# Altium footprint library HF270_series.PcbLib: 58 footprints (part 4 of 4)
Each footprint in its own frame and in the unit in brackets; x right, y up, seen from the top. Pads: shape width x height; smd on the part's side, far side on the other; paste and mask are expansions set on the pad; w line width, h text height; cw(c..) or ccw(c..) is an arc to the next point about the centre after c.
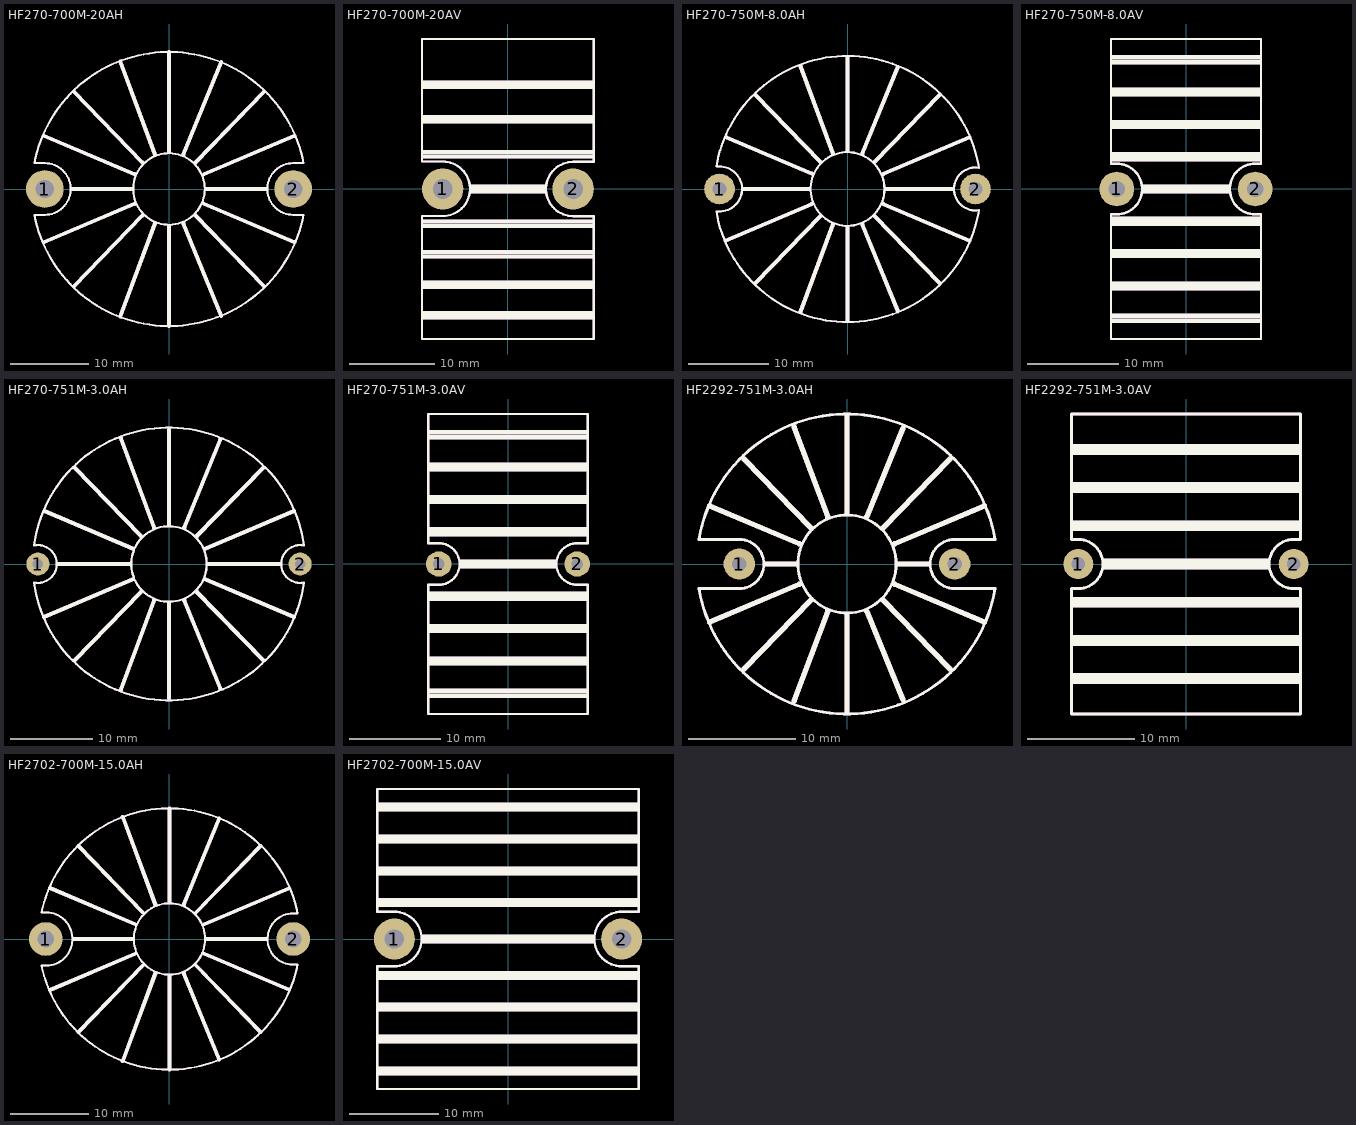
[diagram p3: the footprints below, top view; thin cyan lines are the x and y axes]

## HF270-700M-20AH [mil]
pads (2):
  round 190 hole 92: 1(-625,0) 2(625,0)
Top Overlay:
  circle w10: c0,0 r180
  lines w10: -677.61,-130.18 ccw(c0,0) 677.67,-129.86 ; -677.61,130.18 cw(c0,0) 677.64,130 625,130 ccw(c625,0) 625,-130 677.67,-130 ; -676.66,-130 -625,-130 ccw(c-625,0) -625,130 -676.66,130
  lines w19.68: -630.61,-268.56 -173.05,-74.68 ; -630.61,268.56 -173.05,74.68 ; -485,0 -185,0 ; -479.51,-490.47 -132.7,-132.43 ; -479.51,490.47 -132.7,132.43 ; -245.53,-641.67 -70.44,-171.87 ; -245.53,641.67 -70.44,171.87 ; 0,-690 0,-185 ; 0,185 0,690 ; 72.46,-173.99 262.95,-638.79 ; 72.46,173.99 262.95,638.79 ; 132.5,-132.5 479.53,-490.46 ; 132.5,132.5 479.53,490.46 ; 175.3,-74.28 631.1,-267.41 ; 175.3,74.28 631.1,267.41 ; 185,0 490,0
Mechanical 29:
  circle w10: c0,0 r180
  lines w10: -677.61,-130.18 ccw(c0,0) 677.67,-129.86 ; -677.61,130.18 cw(c0,0) 677.64,130 625,130 ccw(c625,0) 625,-130 677.67,-130 ; -676.66,-130 -625,-130 ccw(c-625,0) -625,130 -676.66,130
  lines w19.68: -630.61,-268.56 -173.05,-74.68 ; -630.61,268.56 -173.05,74.68 ; -485,0 -185,0 ; -479.51,-490.47 -132.7,-132.43 ; -479.51,490.47 -132.7,132.43 ; -245.53,-641.67 -70.44,-171.87 ; -245.53,641.67 -70.44,171.87 ; 0,-690 0,-185 ; 0,185 0,690 ; 72.46,-173.99 262.95,-638.79 ; 72.46,173.99 262.95,638.79 ; 132.5,-132.5 479.53,-490.46 ; 132.5,132.5 479.53,490.46 ; 175.3,-74.28 631.1,-267.41 ; 175.3,74.28 631.1,267.41 ; 185,0 490,0
  text "'.Designator'" at -300,175.15 h400

## HF270-700M-20AV [mil]
pads (2):
  round 190 hole 90: 1(-300,0) 2(300,0)
Top Overlay:
  lines w10: -395,-124.1 -395,-690 395,-690 395,-125 300,-125 cw(c300,0) 300,125 395,125 395,690 -395,690 -395,125.9 ; -394.45,-124.1 -299.45,-124.1 ccw(c-299.45,0.9) -299.45,125.9 -394.45,125.9
  lines w19.68: -390,-590 390,-590 ; -390,-570 390,-570 ; -390,-450 390,-450 ; -390,-430 390,-430 ; -390,-310 390,-310 ; -390,-290 390,-290 ; -390,-170 390,-170 ; -390,-150 390,-150 ; -390,150 390,150 ; -390,170 390,170 ; -390,310 390,310 ; -390,330 390,330 ; -390,470 390,470 ; -390,490 390,490 ; -170,-10 170,-10 ; -170,10 170,10
Mechanical 29:
  lines w10: -395,-124.1 -395,-690 395,-690 395,-125 300,-125 cw(c300,0) 300,125 395,125 395,690 -395,690 -395,125.9 ; -394.45,-124.1 -299.45,-124.1 ccw(c-299.45,0.9) -299.45,125.9 -394.45,125.9
  lines w19.68: -390,-590 390,-590 ; -390,-570 390,-570 ; -390,-450 390,-450 ; -390,-430 390,-430 ; -390,-310 390,-310 ; -390,-290 390,-290 ; -390,-170 390,-170 ; -390,-150 390,-150 ; -390,150 390,150 ; -390,170 390,170 ; -390,310 390,310 ; -390,330 390,330 ; -390,470 390,470 ; -390,490 390,490 ; -170,-10 170,-10 ; -170,10 170,10
  text "'.Designator'" at -1750,-64.85 h400

## HF270-750M-8.0AH [mil]
pads (2):
  round 150 hole 70: 1(-625,0) 2(625,0)
Top Overlay:
  circle w10: c0,0 r180
  lines w10: -640.72,109.47 cw(c0,0) 641.68,103.67 ccw(c625,0) 641.68,-103.67 cw(c0,0) -640.82,-108.86 ccw(c-625,0) -638.75,109.14
  lines w19.68: -596.03,-252.56 -175.3,-74.28 ; -593.79,252.95 -173.05,74.68 ; -510,0 -185,0 ; -450,-460 -132.7,-132.43 ; -450,460 -132.7,132.43 ; -230,-600 -70.44,-171.87 ; -230,600 -70.44,171.87 ; 0,-640 0,-185 ; 0,185 0,640 ; 72.46,-173.99 243.97,-592.47 ; 72.46,173.99 243.97,592.47 ; 132.5,-132.5 450,-460 ; 132.5,132.5 450,460 ; 175.3,-74.28 596.03,-252.56 ; 175.3,74.28 596.03,252.56 ; 185,0 515,0
Mechanical 29:
  circle w10: c0,0 r180
  lines w10: -640.72,109.47 cw(c0,0) 641.68,103.67 ccw(c625,0) 641.68,-103.67 cw(c0,0) -640.82,-108.86 ccw(c-625,0) -638.75,109.14
  lines w19.68: -596.03,-252.56 -175.3,-74.28 ; -593.79,252.95 -173.05,74.68 ; -510,0 -185,0 ; -450,-460 -132.7,-132.43 ; -450,460 -132.7,132.43 ; -230,-600 -70.44,-171.87 ; -230,600 -70.44,171.87 ; 0,-640 0,-185 ; 0,185 0,640 ; 72.46,-173.99 243.97,-592.47 ; 72.46,173.99 243.97,592.47 ; 132.5,-132.5 450,-460 ; 132.5,132.5 450,460 ; 175.3,-74.28 596.03,-252.56 ; 175.3,74.28 596.03,252.56 ; 185,0 515,0
  text "'.Designator'" at -290,145.15 h400

## HF270-750M-8.0AV [mil]
pads (2):
  round 150 hole 70: 1(-300,0) 2(300,0)
Top Overlay:
  lines w10: -325,-650 -325,-110 -300,-110 ccw(c-300,0) -300,110 -325,110 -325,650 325,650 325,110 300,110 ccw(c300,0) 300,-110 325,-110 325,-650 -325,-650
  lines w19.68: -320,-570 320,-570 ; -320,-550 320,-550 ; -320,-430 320,-430 ; -320,-410 320,-410 ; -320,-290 320,-290 ; -320,-270 320,-270 ; -320,-150 320,-150 ; -320,-130 320,-130 ; -320,130 320,130 ; -320,150 320,150 ; -320,270 320,270 ; -320,290 320,290 ; -320,410 320,410 ; -320,430 320,430 ; -320,550 320,550 ; -320,570 320,570 ; -185,-10 185,-10 ; -185,10 185,10
Mechanical 29:
  lines w10: -325,-650 -325,-110 -300,-110 ccw(c-300,0) -300,110 -325,110 -325,650 325,650 325,110 300,110 ccw(c300,0) 300,-110 325,-110 325,-650 -325,-650
  lines w19.68: -320,-570 320,-570 ; -320,-550 320,-550 ; -320,-430 320,-430 ; -320,-410 320,-410 ; -320,-290 320,-290 ; -320,-270 320,-270 ; -320,-150 320,-150 ; -320,-130 320,-130 ; -320,130 320,130 ; -320,150 320,150 ; -320,270 320,270 ; -320,290 320,290 ; -320,410 320,410 ; -320,430 320,430 ; -320,550 320,550 ; -320,570 320,570 ; -185,-10 185,-10 ; -185,10 185,10
  text "'.Designator'" at -1750,-64.85 h400

## HF270-751M-3.0AH [mil]
pads (2):
  round 110 hole 50: 1(-625,0) 2(625,0)
Top Overlay:
  circle w10: c0,0 r180
  lines w10: -644.02,-87.97 ccw(c0,0) 644.02,-87.97 cw(c625,0) 644.02,87.97 ccw(c0,0) -644.02,87.97 cw(c-625,0) -644.02,-87.97
  lines w19.68: -596.03,-252.56 -175.3,-74.28 ; -593.79,252.95 -173.05,74.68 ; -530,0 -185,0 ; -450,-460 -132.7,-132.43 ; -450,460 -132.7,132.43 ; -230,-600 -70.44,-171.87 ; -230,600 -70.44,171.87 ; 0,-640 0,-185 ; 0,185 0,640 ; 72.46,-173.99 243.97,-592.47 ; 72.46,173.99 243.97,592.47 ; 132.5,-132.5 450,-460 ; 132.5,132.5 450,460 ; 175.3,-74.28 596.03,-252.56 ; 175.3,74.28 596.03,252.56 ; 185,0 530,0
Mechanical 29:
  circle w10: c0,0 r180
  lines w10: -644.02,-87.97 ccw(c0,0) 644.02,-87.97 cw(c625,0) 644.02,87.97 ccw(c0,0) -644.02,87.97 cw(c-625,0) -644.02,-87.97
  lines w19.68: -596.03,-252.56 -175.3,-74.28 ; -593.79,252.95 -173.05,74.68 ; -530,0 -185,0 ; -450,-460 -132.7,-132.43 ; -450,460 -132.7,132.43 ; -230,-600 -70.44,-171.87 ; -230,600 -70.44,171.87 ; 0,-640 0,-185 ; 0,185 0,640 ; 72.46,-173.99 243.97,-592.47 ; 72.46,173.99 243.97,592.47 ; 132.5,-132.5 450,-460 ; 132.5,132.5 450,460 ; 175.3,-74.28 596.03,-252.56 ; 175.3,74.28 596.03,252.56 ; 185,0 530,0
  text "'.Designator'" at -290,145.15 h400

## HF270-751M-3.0AV [mil]
pads (2):
  round 110 hole 50: 1(-300,0) 2(300,0)
Top Overlay:
  lines w10: -345,-650 -345,-90 -300,-90 ccw(c-300,0) -300,90 -345,90 -345,650 345,650 345,90 300,90 ccw(c300,0) 300,-90 345,-90 345,-650 -345,-650
  lines w19.68: -340,-570 340,-570 ; -340,-550 340,-550 ; -340,-430 340,-430 ; -340,-410 340,-410 ; -340,-290 340,-290 ; -340,-270 340,-270 ; -340,-150 340,-150 ; -340,-130 340,-130 ; -340,130 340,130 ; -340,150 340,150 ; -340,270 340,270 ; -340,290 340,290 ; -340,410 340,410 ; -340,430 340,430 ; -340,550 340,550 ; -340,570 340,570 ; -205,-10 205,-10 ; -205,10 205,10
Mechanical 29:
  lines w10: -345,-650 -345,-90 -300,-90 ccw(c-300,0) -300,90 -345,90 -345,650 345,650 345,90 300,90 ccw(c300,0) 300,-90 345,-90 345,-650 -345,-650
  lines w19.68: -340,-570 340,-570 ; -340,-550 340,-550 ; -340,-430 340,-430 ; -340,-410 340,-410 ; -340,-290 340,-290 ; -340,-270 340,-270 ; -340,-150 340,-150 ; -340,-130 340,-130 ; -340,130 340,130 ; -340,150 340,150 ; -340,270 340,270 ; -340,290 340,290 ; -340,410 340,410 ; -340,430 340,430 ; -340,550 340,550 ; -340,570 340,570 ; -205,-10 205,-10 ; -205,10 205,10
  text "'.Designator'" at -1750,-64.85 h400

## HF2292-751M-3.0AH [mil]
pads (2):
  round 115 hole 52: 1(-395,0) 2(395,0)
Top Overlay:
  circle w10: c0,0 r180
  lines w10: -543.19,-90 -395,-90 ccw(c-395,0) -395,90 -543.19,90 ; -542.59,-90 ccw(c0,0) 542.6,-89.9 ; -542.6,89.9 cw(c0,0) 542.59,90 ; 543.19,-90 395,-90 cw(c395,0) 395,90 543.19,90
  lines w19.68: -502.92,-213.1 -175.3,-74.28 ; -502.92,213.1 -175.3,74.28 ; -376.13,-383.74 -132.7,-132.43 ; -376.13,383.74 -132.7,132.43 ; -300,0 -185,0 ; -193.62,-502.38 -70.44,-171.87 ; -193.62,502.38 -70.44,171.87 ; 0,-540 0,-185 ; 0,185 0,540 ; 72.46,-173.99 205.19,-497.87 ; 72.46,173.99 205.19,497.87 ; 132.5,-132.5 376.1,-383.78 ; 132.5,132.5 376.1,383.78 ; 175.3,-74.28 502.92,-213.1 ; 175.3,74.28 502.92,213.1 ; 185,0 300,0
Mechanical 29:
  circle w10: c0,0 r180
  lines w10: -543.19,-90 -395,-90 ccw(c-395,0) -395,90 -543.19,90 ; -542.59,-90 ccw(c0,0) 542.6,-89.9 ; -542.6,89.9 cw(c0,0) 542.59,90 ; 543.19,-90 395,-90 cw(c395,0) 395,90 543.19,90
  lines w19.68: -502.92,-213.1 -175.3,-74.28 ; -502.92,213.1 -175.3,74.28 ; -376.13,-383.74 -132.7,-132.43 ; -376.13,383.74 -132.7,132.43 ; -300,0 -185,0 ; -193.62,-502.38 -70.44,-171.87 ; -193.62,502.38 -70.44,171.87 ; 0,-540 0,-185 ; 0,185 0,540 ; 72.46,-173.99 205.19,-497.87 ; 72.46,173.99 205.19,497.87 ; 132.5,-132.5 376.1,-383.78 ; 132.5,132.5 376.1,383.78 ; 175.3,-74.28 502.92,-213.1 ; 175.3,74.28 502.92,213.1 ; 185,0 300,0
  text "'.Designator'" at -290,145.15 h400

## HF2292-751M-3.0AV [mil]
pads (2):
  round 110 hole 50: 1(-395,0) 2(395,0)
Top Overlay:
  lines w10: -420,-550 420,-550 420,-90 395,-90 cw(c395,0) 395,90 420,90 420,550 -420,550 -420,90 -395,90 cw(c-395,0) -395,-90 -420,-90 -420,-550
  lines w19.68: -415,-430 415,-430 ; -415,-410 415,-410 ; -415,-290 415,-290 ; -415,-270 415,-270 ; -415,-150 415,-150 ; -415,-130 415,-130 ; -415,130 415,130 ; -415,150 415,150 ; -415,270 415,270 ; -415,290 415,290 ; -415,410 415,410 ; -415,430 415,430 ; -300,-10 300,-10 ; -300,10 300,10
Mechanical 29:
  lines w10: -420,-550 420,-550 420,-90 395,-90 cw(c395,0) 395,90 420,90 420,550 -420,550 -420,90 -395,90 cw(c-395,0) -395,-90 -420,-90 -420,-550
  lines w19.68: -415,-430 415,-430 ; -415,-410 415,-410 ; -415,-290 415,-290 ; -415,-270 415,-270 ; -415,-150 415,-150 ; -415,-130 415,-130 ; -415,130 415,130 ; -415,150 415,150 ; -415,270 415,270 ; -415,290 415,290 ; -415,410 415,410 ; -415,430 415,430 ; -300,-10 300,-10 ; -300,10 300,10
  text "'.Designator'" at -1750,-64.85 h400

## HF2702-700M-15.0AH [mil]
pads (2):
  round 170 hole 85: 1(-625,0) 2(625,0)
Top Overlay:
  circle w10: c0,0 r180
  lines w10: -646.24,-134.05 ccw(c0,0) 647.3,-128.86 ; -646.24,134.05 cw(c0,0) 647.18,129.44 ; -645.53,133.43 cw(c-625,0) -644.78,-133.54 ; 646.05,-128.28 cw(c625,0) 646.85,128.15
  lines w19.68: -604.03,-257.29 -173.05,-74.68 ; -604.03,257.29 -173.05,74.68 ; -485,0 -185,0 ; -459.92,-470.24 -132.7,-132.43 ; -459.92,470.24 -132.7,132.43 ; -236.54,-617.56 -70.44,-171.87 ; -236.54,617.56 -70.44,171.87 ; 0,-660 0,-185 ; 0,185 0,660 ; 72.46,-173.99 250.98,-609.6 ; 72.46,173.99 250.98,609.6 ; 132.5,-132.5 459.84,-470.15 ; 132.5,132.5 459.84,470.15 ; 175.3,-74.28 604.51,-256.15 ; 175.3,74.28 604.51,256.15 ; 185,0 490,0
Mechanical 29:
  circle w10: c0,0 r180
  lines w10: -646.24,-134.05 ccw(c0,0) 647.3,-128.86 ; -646.24,134.05 cw(c0,0) 647.18,129.44 ; -645.53,133.43 cw(c-625,0) -644.78,-133.54 ; 646.05,-128.28 cw(c625,0) 646.85,128.15
  lines w19.68: -604.03,-257.29 -173.05,-74.68 ; -604.03,257.29 -173.05,74.68 ; -485,0 -185,0 ; -459.92,-470.24 -132.7,-132.43 ; -459.92,470.24 -132.7,132.43 ; -236.54,-617.56 -70.44,-171.87 ; -236.54,617.56 -70.44,171.87 ; 0,-660 0,-185 ; 0,185 0,660 ; 72.46,-173.99 250.98,-609.6 ; 72.46,173.99 250.98,609.6 ; 132.5,-132.5 459.84,-470.15 ; 132.5,132.5 459.84,470.15 ; 175.3,-74.28 604.51,-256.15 ; 175.3,74.28 604.51,256.15 ; 185,0 490,0
  text "'.Designator'" at -292,168.15 h400

## HF2702-700M-15.0AV [mil]
pads (2):
  round 180 hole 85: 1(-500,0) 2(500,0)
Top Overlay:
  lines w10: -575,-660 575,-660 575,-120 500,-120 cw(c500,0) 500,120 575,120 575,660 -575,660 -575,120 -500,120 cw(c-500,0) -500,-120 -575,-120 -575,-660
  lines w19.68: -570,-590 570,-590 ; -570,-570 570,-570 ; -570,-450 570,-450 ; -570,-430 570,-430 ; -570,-310 570,-310 ; -570,-290 570,-290 ; -570,-170 570,-170 ; -570,-150 570,-150 ; -570,150 570,150 ; -570,170 570,170 ; -570,290 570,290 ; -570,310 570,310 ; -570,430 570,430 ; -570,450 570,450 ; -570,570 570,570 ; -570,590 570,590 ; -375,-10 375,-10 ; -375,10 375,10
Mechanical 29:
  lines w10: -575,-660 575,-660 575,-120 500,-120 cw(c500,0) 500,120 575,120 575,660 -575,660 -575,120 -500,120 cw(c-500,0) -500,-120 -575,-120 -575,-660
  lines w19.68: -570,-590 570,-590 ; -570,-570 570,-570 ; -570,-450 570,-450 ; -570,-430 570,-430 ; -570,-310 570,-310 ; -570,-290 570,-290 ; -570,-170 570,-170 ; -570,-150 570,-150 ; -570,150 570,150 ; -570,170 570,170 ; -570,290 570,290 ; -570,310 570,310 ; -570,430 570,430 ; -570,450 570,450 ; -570,570 570,570 ; -570,590 570,590 ; -375,-10 375,-10 ; -375,10 375,10
  text "'.Designator'" at -1750,-64.85 h400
